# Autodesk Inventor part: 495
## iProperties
Author: Administrator
Shininess: 64.0
Angle Display Precision: 2
Document Length Units: 11272
Document Angle Units: 11286
Document Time Units: 11279
Document Mass Units: 11290
Document Length Units Precision: 3
Document Angle Units Precision: 2
Compacted: True
PropertySet Name: _Private Model Information
Created: 2002-03
Part Number: 495
Material: Stainless Steel, 440C
Document SubType Name: Modeling
Designer: Administrator
Control State: 0
Master: False
Checked Out: False
PropertySet Name: Design Tracking Control
Density: 0.0
Volumn: 0.0
Area: 0.0
PropertySet Name: Model Information
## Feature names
1. Revolution1
